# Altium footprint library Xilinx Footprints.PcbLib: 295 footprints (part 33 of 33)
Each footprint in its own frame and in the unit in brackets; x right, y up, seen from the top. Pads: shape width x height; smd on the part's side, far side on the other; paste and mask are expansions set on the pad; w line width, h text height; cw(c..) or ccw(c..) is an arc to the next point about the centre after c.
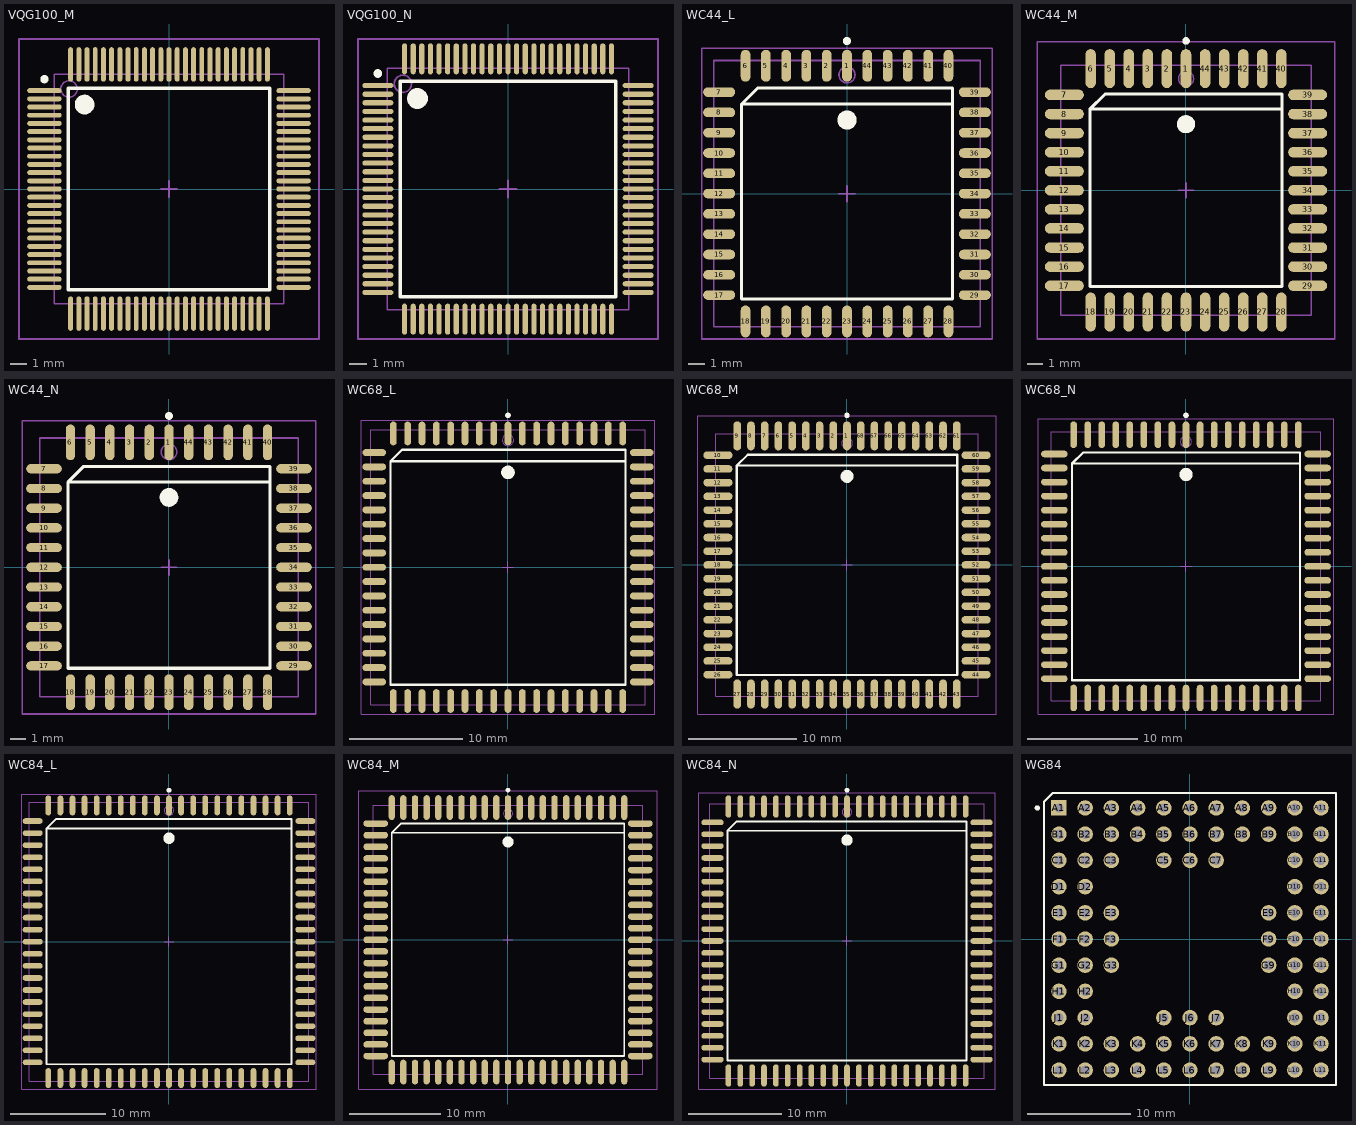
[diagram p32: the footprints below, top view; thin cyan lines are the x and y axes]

## VQG100_M [mm] "100-Pin Very Thin Quad Flat Pack (VQG100) - Pb-Free, IPC Low Density"
height 1.2
pads (100):
  oval 2.1x0.3 smd: 1(-7.6,6) 2(-7.6,5.5) 3(-7.6,5) 4(-7.6,4.5) 5(-7.6,4) 6(-7.6,3.5) 7(-7.6,3) 8(-7.6,2.5) 9(-7.6,2) 10(-7.6,1.5) 11(-7.6,1) 12(-7.6,0.5) 13(-7.6,0) 14(-7.6,-0.5) 15(-7.6,-1) 16(-7.6,-1.5) 17(-7.6,-2) 18(-7.6,-2.5) 19(-7.6,-3) 20(-7.6,-3.5) 21(-7.6,-4) 22(-7.6,-4.5) 23(-7.6,-5) 24(-7.6,-5.5) 25(-7.6,-6) 51(7.6,-6) 52(7.6,-5.5) 53(7.6,-5) 54(7.6,-4.5) 55(7.6,-4) 56(7.6,-3.5) 57(7.6,-3) 58(7.6,-2.5) 59(7.6,-2) 60(7.6,-1.5) 61(7.6,-1) 62(7.6,-0.5) 63(7.6,0) 64(7.6,0.5) 65(7.6,1) 66(7.6,1.5) 67(7.6,2) 68(7.6,2.5) 69(7.6,3) 70(7.6,3.5) 71(7.6,4) 72(7.6,4.5) 73(7.6,5) 74(7.6,5.5) 75(7.6,6)
  oval 0.3x2.1 smd: 26(-6,-7.6) 27(-5.5,-7.6) 28(-5,-7.6) 29(-4.5,-7.6) 30(-4,-7.6) 31(-3.5,-7.6) 32(-3,-7.6) 33(-2.5,-7.6) 34(-2,-7.6) 35(-1.5,-7.6) 36(-1,-7.6) 37(-0.5,-7.6) 38(0,-7.6) 39(0.5,-7.6) 40(1,-7.6) 41(1.5,-7.6) 42(2,-7.6) 43(2.5,-7.6) 44(3,-7.6) 45(3.5,-7.6) 46(4,-7.6) 47(4.5,-7.6) 48(5,-7.6) 49(5.5,-7.6) 50(6,-7.6) 76(6,7.6) 77(5.5,7.6) 78(5,7.6) 79(4.5,7.6) 80(4,7.6) 81(3.5,7.6) 82(3,7.6) 83(2.5,7.6) 84(2,7.6) 85(1.5,7.6) 86(1,7.6) 87(0.5,7.6) 88(0,7.6) 89(-0.5,7.6) 90(-1,7.6) 91(-1.5,7.6) 92(-2,7.6) 93(-2.5,7.6) 94(-3,7.6) 95(-3.5,7.6) 96(-4,7.6) 97(-4.5,7.6) 98(-5,7.6) 99(-5.5,7.6) 100(-6,7.6)
Top Overlay:
  circle w0.6: c-5.15,5.15 r0.3
  circle w0.25: c-7.6,6.7 r0.125
  lines w0.2: -6.15,-6.15 6.15,-6.15 6.15,6.15 -6.15,6.15 -6.15,-6.15
Mechanical 13:
  circle w0.1: c-6.1,6.1 r0.5
  lines w0.1: -7,-7 7,-7 7,7 -7,7 -7,-7
Mechanical 15:
  lines w0.1: -0.5,0 0.5,0 ; 0,-0.5 0,0.5 ; -9.15,-9.15 9.15,-9.15 9.15,9.15 -9.15,9.15 -9.15,-9.15
3D body: height 1.2, standoff 0, extent -7,-7 7,7

## VQG100_N [mm] "100-Pin Very Thin Quad Flat Pack (VQG100) - Pb-Free, IPC Medium Density"
height 1.2
pads (100):
  oval 1.8x0.3 smd: 1(-7.55,6) 2(-7.55,5.5) 3(-7.55,5) 4(-7.55,4.5) 5(-7.55,4) 6(-7.55,3.5) 7(-7.55,3) 8(-7.55,2.5) 9(-7.55,2) 10(-7.55,1.5) 11(-7.55,1) 12(-7.55,0.5) 13(-7.55,0) 14(-7.55,-0.5) 15(-7.55,-1) 16(-7.55,-1.5) 17(-7.55,-2) 18(-7.55,-2.5) 19(-7.55,-3) 20(-7.55,-3.5) 21(-7.55,-4) 22(-7.55,-4.5) 23(-7.55,-5) 24(-7.55,-5.5) 25(-7.55,-6) 51(7.55,-6) 52(7.55,-5.5) 53(7.55,-5) 54(7.55,-4.5) 55(7.55,-4) 56(7.55,-3.5) 57(7.55,-3) 58(7.55,-2.5) 59(7.55,-2) 60(7.55,-1.5) 61(7.55,-1) 62(7.55,-0.5) 63(7.55,0) 64(7.55,0.5) 65(7.55,1) 66(7.55,1.5) 67(7.55,2) 68(7.55,2.5) 69(7.55,3) 70(7.55,3.5) 71(7.55,4) 72(7.55,4.5) 73(7.55,5) 74(7.55,5.5) 75(7.55,6)
  oval 0.3x1.8 smd: 26(-6,-7.55) 27(-5.5,-7.55) 28(-5,-7.55) 29(-4.5,-7.55) 30(-4,-7.55) 31(-3.5,-7.55) 32(-3,-7.55) 33(-2.5,-7.55) 34(-2,-7.55) 35(-1.5,-7.55) 36(-1,-7.55) 37(-0.5,-7.55) 38(0,-7.55) 39(0.5,-7.55) 40(1,-7.55) 41(1.5,-7.55) 42(2,-7.55) 43(2.5,-7.55) 44(3,-7.55) 45(3.5,-7.55) 46(4,-7.55) 47(4.5,-7.55) 48(5,-7.55) 49(5.5,-7.55) 50(6,-7.55) 76(6,7.55) 77(5.5,7.55) 78(5,7.55) 79(4.5,7.55) 80(4,7.55) 81(3.5,7.55) 82(3,7.55) 83(2.5,7.55) 84(2,7.55) 85(1.5,7.55) 86(1,7.55) 87(0.5,7.55) 88(0,7.55) 89(-0.5,7.55) 90(-1,7.55) 91(-1.5,7.55) 92(-2,7.55) 93(-2.5,7.55) 94(-3,7.55) 95(-3.5,7.55) 96(-4,7.55) 97(-4.5,7.55) 98(-5,7.55) 99(-5.5,7.55) 100(-6,7.55)
Top Overlay:
  circle w0.6: c-5.25,5.25 r0.3
  circle w0.25: c-7.55,6.7 r0.125
  lines w0.2: -6.25,-6.25 6.25,-6.25 6.25,6.25 -6.25,6.25 -6.25,-6.25
Mechanical 13:
  circle w0.1: c-6.1,6.1 r0.5
  lines w0.1: -7,-7 7,-7 7,7 -7,7 -7,-7
Mechanical 15:
  lines w0.1: -0.5,0 0.5,0 ; 0,-0.5 0,0.5 ; -8.7,-8.7 8.7,-8.7 8.7,8.7 -8.7,8.7 -8.7,-8.7
3D body: height 1.2, standoff 0, extent -7,-7 7,7

## WC44_L [mm] "44-Pin Window Ceramic Leaded Chip Carrier (WC44), IPC High Density"
height 4.83
pads (44):
  oval 0.6x2 smd: 1(0,8) 2(-1.27,8) 3(-2.54,8) 4(-3.81,8) 5(-5.08,8) 6(-6.35,8) 18(-6.35,-8) 19(-5.08,-8) 20(-3.81,-8) 21(-2.54,-8) 22(-1.27,-8) 23(0,-8) 24(1.27,-8) 25(2.54,-8) 26(3.81,-8) 27(5.08,-8) 28(6.35,-8) 40(6.35,8) 41(5.08,8) 42(3.81,8) 43(2.54,8) 44(1.27,8)
  oval 2x0.6 smd: 7(-8,6.35) 8(-8,5.08) 9(-8,3.81) 10(-8,2.54) 11(-8,1.27) 12(-8,0) 13(-8,-1.27) 14(-8,-2.54) 15(-8,-3.81) 16(-8,-5.08) 17(-8,-6.35) 29(8,-6.35) 30(8,-5.08) 31(8,-3.81) 32(8,-2.54) 33(8,-1.27) 34(8,0) 35(8,1.27) 36(8,2.54) 37(8,3.81) 38(8,5.08) 39(8,6.35)
Top Overlay:
  circle w0.25: c0,9.55 r0.125
  circle w0.6: c0,4.6 r0.3
  lines w0.2: 6.6,5.6 -6.6,5.6 ; -6.6,5.6 -5.6,6.6 6.6,6.6 6.6,-6.6 -6.6,-6.6 -6.6,5.6
Mechanical 13:
  circle w0.1: c0,7.43 r0.5
  lines w0.1: -8.33,-8.33 -8.33,8.33 8.33,8.33 8.33,-8.33 -8.33,-8.33
Mechanical 15:
  lines w0.1: -0.5,0 0.5,0 ; 0,-0.5 0,0.5 ; -9.1,-9.1 -9.1,9.1 9.1,9.1 9.1,-9.1 -9.1,-9.1
3D body: height 4.83, standoff 0, extent -8.33,-8.33 8.33,8.33

## WC44_M [mm] "44-Pin Window Ceramic Leaded Chip Carrier (WC44), IPC Low Density"
height 4.83
pads (44):
  oval 0.7x2.6 smd: 1(0,8.1) 2(-1.27,8.1) 3(-2.54,8.1) 4(-3.81,8.1) 5(-5.08,8.1) 6(-6.35,8.1) 18(-6.35,-8.1) 19(-5.08,-8.1) 20(-3.81,-8.1) 21(-2.54,-8.1) 22(-1.27,-8.1) 23(0,-8.1) 24(1.27,-8.1) 25(2.54,-8.1) 26(3.81,-8.1) 27(5.08,-8.1) 28(6.35,-8.1) 40(6.35,8.1) 41(5.08,8.1) 42(3.81,8.1) 43(2.54,8.1) 44(1.27,8.1)
  oval 2.6x0.7 smd: 7(-8.1,6.35) 8(-8.1,5.08) 9(-8.1,3.81) 10(-8.1,2.54) 11(-8.1,1.27) 12(-8.1,0) 13(-8.1,-1.27) 14(-8.1,-2.54) 15(-8.1,-3.81) 16(-8.1,-5.08) 17(-8.1,-6.35) 29(8.1,-6.35) 30(8.1,-5.08) 31(8.1,-3.81) 32(8.1,-2.54) 33(8.1,-1.27) 34(8.1,0) 35(8.1,1.27) 36(8.1,2.54) 37(8.1,3.81) 38(8.1,5.08) 39(8.1,6.35)
Top Overlay:
  circle w0.25: c0,9.95 r0.125
  circle w0.6: c0,4.4 r0.3
  lines w0.2: 6.4,5.4 -6.4,5.4 ; -6.4,5.4 -5.4,6.4 6.4,6.4 6.4,-6.4 -6.4,-6.4 -6.4,5.4
Mechanical 13:
  circle w0.1: c0,7.43 r0.5
  lines w0.1: -8.33,-8.33 -8.33,8.33 8.33,8.33 8.33,-8.33 -8.33,-8.33
Mechanical 15:
  lines w0.1: -0.5,0 0.5,0 ; 0,-0.5 0,0.5 ; -9.9,-9.9 -9.9,9.9 9.9,9.9 9.9,-9.9 -9.9,-9.9
3D body: height 4.83, standoff 0, extent -8.33,-8.33 8.33,8.33

## WC44_N [mm] "44-Pin Window Ceramic Leaded Chip Carrier (WC44), IPC Medium Density"
height 4.83
pads (44):
  oval 0.6x2.3 smd: 1(0,8.05) 2(-1.27,8.05) 3(-2.54,8.05) 4(-3.81,8.05) 5(-5.08,8.05) 6(-6.35,8.05) 18(-6.35,-8.05) 19(-5.08,-8.05) 20(-3.81,-8.05) 21(-2.54,-8.05) 22(-1.27,-8.05) 23(0,-8.05) 24(1.27,-8.05) 25(2.54,-8.05) 26(3.81,-8.05) 27(5.08,-8.05) 28(6.35,-8.05) 40(6.35,8.05) 41(5.08,8.05) 42(3.81,8.05) 43(2.54,8.05) 44(1.27,8.05)
  oval 2.3x0.6 smd: 7(-8.05,6.35) 8(-8.05,5.08) 9(-8.05,3.81) 10(-8.05,2.54) 11(-8.05,1.27) 12(-8.05,0) 13(-8.05,-1.27) 14(-8.05,-2.54) 15(-8.05,-3.81) 16(-8.05,-5.08) 17(-8.05,-6.35) 29(8.05,-6.35) 30(8.05,-5.08) 31(8.05,-3.81) 32(8.05,-2.54) 33(8.05,-1.27) 34(8.05,0) 35(8.05,1.27) 36(8.05,2.54) 37(8.05,3.81) 38(8.05,5.08) 39(8.05,6.35)
Top Overlay:
  circle w0.25: c0,9.75 r0.125
  circle w0.6: c0,4.5 r0.3
  lines w0.2: 6.5,5.5 -6.5,5.5 ; -6.5,5.5 -5.5,6.5 6.5,6.5 6.5,-6.5 -6.5,-6.5 -6.5,5.5
Mechanical 13:
  circle w0.1: c0,7.43 r0.5
  lines w0.1: -8.33,-8.33 -8.33,8.33 8.33,8.33 8.33,-8.33 -8.33,-8.33
Mechanical 15:
  lines w0.1: -0.5,0 0.5,0 ; 0,-0.5 0,0.5 ; -9.45,-9.45 -9.45,9.45 9.45,9.45 9.45,-9.45 -9.45,-9.45
3D body: height 4.83, standoff 0, extent -8.33,-8.33 8.33,8.33

## WC68_L [mm] "68-Pin Window Ceramic Leaded Chip Carrier (WC68), IPC High Density"
height 4.83
pads (68):
  oval 0.6x2.1 smd: 1(0,11.85) 2(-1.27,11.85) 3(-2.54,11.85) 4(-3.81,11.85) 5(-5.08,11.85) 6(-6.35,11.85) 7(-7.62,11.85) 8(-8.89,11.85) 9(-10.16,11.85) 27(-10.16,-11.85) 28(-8.89,-11.85) 29(-7.62,-11.85) 30(-6.35,-11.85) 31(-5.08,-11.85) 32(-3.81,-11.85) 33(-2.54,-11.85) 34(-1.27,-11.85) 35(0,-11.85) 36(1.27,-11.85) 37(2.54,-11.85) 38(3.81,-11.85) 39(5.08,-11.85) 40(6.35,-11.85) 41(7.62,-11.85) 42(8.89,-11.85) 43(10.16,-11.85) 61(10.16,11.85) 62(8.89,11.85) 63(7.62,11.85) 64(6.35,11.85) 65(5.08,11.85) 66(3.81,11.85) 67(2.54,11.85) 68(1.27,11.85)
  oval 2.1x0.6 smd: 10(-11.85,10.16) 11(-11.85,8.89) 12(-11.85,7.62) 13(-11.85,6.35) 14(-11.85,5.08) 15(-11.85,3.81) 16(-11.85,2.54) 17(-11.85,1.27) 18(-11.85,0) 19(-11.85,-1.27) 20(-11.85,-2.54) 21(-11.85,-3.81) 22(-11.85,-5.08) 23(-11.85,-6.35) 24(-11.85,-7.62) 25(-11.85,-8.89) 26(-11.85,-10.16) 44(11.85,-10.16) 45(11.85,-8.89) 46(11.85,-7.62) 47(11.85,-6.35) 48(11.85,-5.08) 49(11.85,-3.81) 50(11.85,-2.54) 51(11.85,-1.27) 52(11.85,0) 53(11.85,1.27) 54(11.85,2.54) 55(11.85,3.81) 56(11.85,5.08) 57(11.85,6.35) 58(11.85,7.62) 59(11.85,8.89) 60(11.85,10.16)
Top Overlay:
  circle w0.25: c0,13.45 r0.125
  circle w0.6: c0,8.4 r0.3
  lines w0.2: 10.4,9.4 -10.4,9.4 ; -10.4,9.4 -9.4,10.4 10.4,10.4 10.4,-10.4 -10.4,-10.4 -10.4,9.4
Mechanical 13:
  circle w0.1: c0,11.265 r0.5
  lines w0.1: -12.165,-12.165 -12.165,12.165 12.165,12.165 12.165,-12.165 -12.165,-12.165
Mechanical 15:
  lines w0.1: -0.5,0 0.5,0 ; 0,-0.5 0,0.5 ; -13,-13 -13,13 13,13 13,-13 -13,-13
3D body: height 4.83, standoff 0, extent -12.165,-12.165 12.165,12.165

## WC68_M [mm] "68-Pin Window Ceramic Leaded Chip Carrier (WC68), IPC Low Density"
height 4.83
pads (68):
  oval 0.7x2.7 smd: 1(0,11.95) 2(-1.27,11.95) 3(-2.54,11.95) 4(-3.81,11.95) 5(-5.08,11.95) 6(-6.35,11.95) 7(-7.62,11.95) 8(-8.89,11.95) 9(-10.16,11.95) 27(-10.16,-11.95) 28(-8.89,-11.95) 29(-7.62,-11.95) 30(-6.35,-11.95) 31(-5.08,-11.95) 32(-3.81,-11.95) 33(-2.54,-11.95) 34(-1.27,-11.95) 35(0,-11.95) 36(1.27,-11.95) 37(2.54,-11.95) 38(3.81,-11.95) 39(5.08,-11.95) 40(6.35,-11.95) 41(7.62,-11.95) 42(8.89,-11.95) 43(10.16,-11.95) 61(10.16,11.95) 62(8.89,11.95) 63(7.62,11.95) 64(6.35,11.95) 65(5.08,11.95) 66(3.81,11.95) 67(2.54,11.95) 68(1.27,11.95)
  oval 2.7x0.7 smd: 10(-11.95,10.16) 11(-11.95,8.89) 12(-11.95,7.62) 13(-11.95,6.35) 14(-11.95,5.08) 15(-11.95,3.81) 16(-11.95,2.54) 17(-11.95,1.27) 18(-11.95,0) 19(-11.95,-1.27) 20(-11.95,-2.54) 21(-11.95,-3.81) 22(-11.95,-5.08) 23(-11.95,-6.35) 24(-11.95,-7.62) 25(-11.95,-8.89) 26(-11.95,-10.16) 44(11.95,-10.16) 45(11.95,-8.89) 46(11.95,-7.62) 47(11.95,-6.35) 48(11.95,-5.08) 49(11.95,-3.81) 50(11.95,-2.54) 51(11.95,-1.27) 52(11.95,0) 53(11.95,1.27) 54(11.95,2.54) 55(11.95,3.81) 56(11.95,5.08) 57(11.95,6.35) 58(11.95,7.62) 59(11.95,8.89) 60(11.95,10.16)
Top Overlay:
  circle w0.25: c0,13.85 r0.125
  circle w0.6: c0,8.2 r0.3
  lines w0.2: 10.2,9.2 -10.2,9.2 ; -10.2,9.2 -9.2,10.2 10.2,10.2 10.2,-10.2 -10.2,-10.2 -10.2,9.2
Mechanical 13:
  circle w0.1: c0,11.265 r0.5
  lines w0.1: -12.165,-12.165 -12.165,12.165 12.165,12.165 12.165,-12.165 -12.165,-12.165
Mechanical 15:
  lines w0.1: -0.5,0 0.5,0 ; 0,-0.5 0,0.5 ; -13.8,-13.8 -13.8,13.8 13.8,13.8 13.8,-13.8 -13.8,-13.8
3D body: height 4.83, standoff 0, extent -12.165,-12.165 12.165,12.165

## WC68_N [mm] "68-Pin Window Ceramic Leaded Chip Carrier (WC68), IPC Medium Density"
height 4.83
pads (68):
  oval 0.6x2.4 smd: 1(0,11.9) 2(-1.27,11.9) 3(-2.54,11.9) 4(-3.81,11.9) 5(-5.08,11.9) 6(-6.35,11.9) 7(-7.62,11.9) 8(-8.89,11.9) 9(-10.16,11.9) 27(-10.16,-11.9) 28(-8.89,-11.9) 29(-7.62,-11.9) 30(-6.35,-11.9) 31(-5.08,-11.9) 32(-3.81,-11.9) 33(-2.54,-11.9) 34(-1.27,-11.9) 35(0,-11.9) 36(1.27,-11.9) 37(2.54,-11.9) 38(3.81,-11.9) 39(5.08,-11.9) 40(6.35,-11.9) 41(7.62,-11.9) 42(8.89,-11.9) 43(10.16,-11.9) 61(10.16,11.9) 62(8.89,11.9) 63(7.62,11.9) 64(6.35,11.9) 65(5.08,11.9) 66(3.81,11.9) 67(2.54,11.9) 68(1.27,11.9)
  oval 2.4x0.6 smd: 10(-11.9,10.16) 11(-11.9,8.89) 12(-11.9,7.62) 13(-11.9,6.35) 14(-11.9,5.08) 15(-11.9,3.81) 16(-11.9,2.54) 17(-11.9,1.27) 18(-11.9,0) 19(-11.9,-1.27) 20(-11.9,-2.54) 21(-11.9,-3.81) 22(-11.9,-5.08) 23(-11.9,-6.35) 24(-11.9,-7.62) 25(-11.9,-8.89) 26(-11.9,-10.16) 44(11.9,-10.16) 45(11.9,-8.89) 46(11.9,-7.62) 47(11.9,-6.35) 48(11.9,-5.08) 49(11.9,-3.81) 50(11.9,-2.54) 51(11.9,-1.27) 52(11.9,0) 53(11.9,1.27) 54(11.9,2.54) 55(11.9,3.81) 56(11.9,5.08) 57(11.9,6.35) 58(11.9,7.62) 59(11.9,8.89) 60(11.9,10.16)
Top Overlay:
  circle w0.25: c0,13.65 r0.125
  circle w0.6: c0,8.3 r0.3
  lines w0.2: 10.3,9.3 -10.3,9.3 ; -10.3,9.3 -9.3,10.3 10.3,10.3 10.3,-10.3 -10.3,-10.3 -10.3,9.3
Mechanical 13:
  circle w0.1: c0,11.265 r0.5
  lines w0.1: -12.165,-12.165 -12.165,12.165 12.165,12.165 12.165,-12.165 -12.165,-12.165
Mechanical 15:
  lines w0.1: -0.5,0 0.5,0 ; 0,-0.5 0,0.5 ; -13.35,-13.35 -13.35,13.35 13.35,13.35 13.35,-13.35 -13.35,-13.35
3D body: height 4.83, standoff 0, extent -12.165,-12.165 12.165,12.165

## WC84_L [mm] "84-Pin Window Ceramic Leaded Chip Carrier (WC84), IPC High Density"
height 4.83
pads (84):
  oval 0.6x2.1 smd: 1(0,14.35) 2(-1.27,14.35) 3(-2.54,14.35) 4(-3.81,14.35) 5(-5.08,14.35) 6(-6.35,14.35) 7(-7.62,14.35) 8(-8.89,14.35) 9(-10.16,14.35) 10(-11.43,14.35) 11(-12.7,14.35) 33(-12.7,-14.35) 34(-11.43,-14.35) 35(-10.16,-14.35) 36(-8.89,-14.35) 37(-7.62,-14.35) 38(-6.35,-14.35) 39(-5.08,-14.35) 40(-3.81,-14.35) 41(-2.54,-14.35) 42(-1.27,-14.35) 43(0,-14.35) 44(1.27,-14.35) 45(2.54,-14.35) 46(3.81,-14.35) 47(5.08,-14.35) 48(6.35,-14.35) 49(7.62,-14.35) 50(8.89,-14.35) 51(10.16,-14.35) 52(11.43,-14.35) 53(12.7,-14.35) 75(12.7,14.35) 76(11.43,14.35) 77(10.16,14.35) 78(8.89,14.35) 79(7.62,14.35) 80(6.35,14.35) 81(5.08,14.35) 82(3.81,14.35) 83(2.54,14.35) 84(1.27,14.35)
  oval 2.1x0.6 smd: 12(-14.35,12.7) 13(-14.35,11.43) 14(-14.35,10.16) 15(-14.35,8.89) 16(-14.35,7.62) 17(-14.35,6.35) 18(-14.35,5.08) 19(-14.35,3.81) 20(-14.35,2.54) 21(-14.35,1.27) 22(-14.35,0) 23(-14.35,-1.27) 24(-14.35,-2.54) 25(-14.35,-3.81) 26(-14.35,-5.08) 27(-14.35,-6.35) 28(-14.35,-7.62) 29(-14.35,-8.89) 30(-14.35,-10.16) 31(-14.35,-11.43) 32(-14.35,-12.7) 54(14.35,-12.7) 55(14.35,-11.43) 56(14.35,-10.16) 57(14.35,-8.89) 58(14.35,-7.62) 59(14.35,-6.35) 60(14.35,-5.08) 61(14.35,-3.81) 62(14.35,-2.54) 63(14.35,-1.27) 64(14.35,0) 65(14.35,1.27) 66(14.35,2.54) 67(14.35,3.81) 68(14.35,5.08) 69(14.35,6.35) 70(14.35,7.62) 71(14.35,8.89) 72(14.35,10.16) 73(14.35,11.43) 74(14.35,12.7)
Top Overlay:
  circle w0.25: c0,15.95 r0.125
  circle w0.6: c0,10.9 r0.3
  lines w0.2: 12.9,11.9 -12.9,11.9 ; -12.9,11.9 -11.9,12.9 12.9,12.9 12.9,-12.9 -12.9,-12.9 -12.9,11.9
Mechanical 13:
  circle w0.1: c0,13.805 r0.5
  lines w0.1: -14.705,-14.705 -14.705,14.705 14.705,14.705 14.705,-14.705 -14.705,-14.705
Mechanical 15:
  lines w0.1: -0.5,0 0.5,0 ; 0,-0.5 0,0.5 ; -15.5,-15.5 -15.5,15.5 15.5,15.5 15.5,-15.5 -15.5,-15.5
3D body: height 4.83, standoff 0, extent -14.705,-14.705 14.705,14.705

## WC84_M [mm] "84-Pin Window Ceramic Leaded Chip Carrier (WC84), IPC Low Density"
height 4.83
pads (84):
  oval 0.7x2.7 smd: 1(0,14.45) 2(-1.27,14.45) 3(-2.54,14.45) 4(-3.81,14.45) 5(-5.08,14.45) 6(-6.35,14.45) 7(-7.62,14.45) 8(-8.89,14.45) 9(-10.16,14.45) 10(-11.43,14.45) 11(-12.7,14.45) 33(-12.7,-14.45) 34(-11.43,-14.45) 35(-10.16,-14.45) 36(-8.89,-14.45) 37(-7.62,-14.45) 38(-6.35,-14.45) 39(-5.08,-14.45) 40(-3.81,-14.45) 41(-2.54,-14.45) 42(-1.27,-14.45) 43(0,-14.45) 44(1.27,-14.45) 45(2.54,-14.45) 46(3.81,-14.45) 47(5.08,-14.45) 48(6.35,-14.45) 49(7.62,-14.45) 50(8.89,-14.45) 51(10.16,-14.45) 52(11.43,-14.45) 53(12.7,-14.45) 75(12.7,14.45) 76(11.43,14.45) 77(10.16,14.45) 78(8.89,14.45) 79(7.62,14.45) 80(6.35,14.45) 81(5.08,14.45) 82(3.81,14.45) 83(2.54,14.45) 84(1.27,14.45)
  oval 2.7x0.7 smd: 12(-14.45,12.7) 13(-14.45,11.43) 14(-14.45,10.16) 15(-14.45,8.89) 16(-14.45,7.62) 17(-14.45,6.35) 18(-14.45,5.08) 19(-14.45,3.81) 20(-14.45,2.54) 21(-14.45,1.27) 22(-14.45,0) 23(-14.45,-1.27) 24(-14.45,-2.54) 25(-14.45,-3.81) 26(-14.45,-5.08) 27(-14.45,-6.35) 28(-14.45,-7.62) 29(-14.45,-8.89) 30(-14.45,-10.16) 31(-14.45,-11.43) 32(-14.45,-12.7) 54(14.45,-12.7) 55(14.45,-11.43) 56(14.45,-10.16) 57(14.45,-8.89) 58(14.45,-7.62) 59(14.45,-6.35) 60(14.45,-5.08) 61(14.45,-3.81) 62(14.45,-2.54) 63(14.45,-1.27) 64(14.45,0) 65(14.45,1.27) 66(14.45,2.54) 67(14.45,3.81) 68(14.45,5.08) 69(14.45,6.35) 70(14.45,7.62) 71(14.45,8.89) 72(14.45,10.16) 73(14.45,11.43) 74(14.45,12.7)
Top Overlay:
  circle w0.25: c0,16.35 r0.125
  circle w0.6: c0,10.7 r0.3
  lines w0.2: 12.7,11.7 -12.7,11.7 ; -12.7,11.7 -11.7,12.7 12.7,12.7 12.7,-12.7 -12.7,-12.7 -12.7,11.7
Mechanical 13:
  circle w0.1: c0,13.805 r0.5
  lines w0.1: -14.705,-14.705 -14.705,14.705 14.705,14.705 14.705,-14.705 -14.705,-14.705
Mechanical 15:
  lines w0.1: -0.5,0 0.5,0 ; 0,-0.5 0,0.5 ; -16.3,-16.3 -16.3,16.3 16.3,16.3 16.3,-16.3 -16.3,-16.3
3D body: height 4.83, standoff 0, extent -14.705,-14.705 14.705,14.705

## WC84_N [mm] "84-Pin Window Ceramic Leaded Chip Carrier (WC84), IPC Medium Density"
height 4.83
pads (84):
  oval 0.6x2.4 smd: 1(0,14.4) 2(-1.27,14.4) 3(-2.54,14.4) 4(-3.81,14.4) 5(-5.08,14.4) 6(-6.35,14.4) 7(-7.62,14.4) 8(-8.89,14.4) 9(-10.16,14.4) 10(-11.43,14.4) 11(-12.7,14.4) 33(-12.7,-14.4) 34(-11.43,-14.4) 35(-10.16,-14.4) 36(-8.89,-14.4) 37(-7.62,-14.4) 38(-6.35,-14.4) 39(-5.08,-14.4) 40(-3.81,-14.4) 41(-2.54,-14.4) 42(-1.27,-14.4) 43(0,-14.4) 44(1.27,-14.4) 45(2.54,-14.4) 46(3.81,-14.4) 47(5.08,-14.4) 48(6.35,-14.4) 49(7.62,-14.4) 50(8.89,-14.4) 51(10.16,-14.4) 52(11.43,-14.4) 53(12.7,-14.4) 75(12.7,14.4) 76(11.43,14.4) 77(10.16,14.4) 78(8.89,14.4) 79(7.62,14.4) 80(6.35,14.4) 81(5.08,14.4) 82(3.81,14.4) 83(2.54,14.4) 84(1.27,14.4)
  oval 2.4x0.6 smd: 12(-14.4,12.7) 13(-14.4,11.43) 14(-14.4,10.16) 15(-14.4,8.89) 16(-14.4,7.62) 17(-14.4,6.35) 18(-14.4,5.08) 19(-14.4,3.81) 20(-14.4,2.54) 21(-14.4,1.27) 22(-14.4,0) 23(-14.4,-1.27) 24(-14.4,-2.54) 25(-14.4,-3.81) 26(-14.4,-5.08) 27(-14.4,-6.35) 28(-14.4,-7.62) 29(-14.4,-8.89) 30(-14.4,-10.16) 31(-14.4,-11.43) 32(-14.4,-12.7) 54(14.4,-12.7) 55(14.4,-11.43) 56(14.4,-10.16) 57(14.4,-8.89) 58(14.4,-7.62) 59(14.4,-6.35) 60(14.4,-5.08) 61(14.4,-3.81) 62(14.4,-2.54) 63(14.4,-1.27) 64(14.4,0) 65(14.4,1.27) 66(14.4,2.54) 67(14.4,3.81) 68(14.4,5.08) 69(14.4,6.35) 70(14.4,7.62) 71(14.4,8.89) 72(14.4,10.16) 73(14.4,11.43) 74(14.4,12.7)
Top Overlay:
  circle w0.25: c0,16.15 r0.125
  circle w0.6: c0,10.8 r0.3
  lines w0.2: 12.8,11.8 -12.8,11.8 ; -12.8,11.8 -11.8,12.8 12.8,12.8 12.8,-12.8 -12.8,-12.8 -12.8,11.8
Mechanical 13:
  circle w0.1: c0,13.805 r0.5
  lines w0.1: -14.705,-14.705 -14.705,14.705 14.705,14.705 14.705,-14.705 -14.705,-14.705
Mechanical 15:
  lines w0.1: -0.5,0 0.5,0 ; 0,-0.5 0,0.5 ; -15.85,-15.85 -15.85,15.85 15.85,15.85 15.85,-15.85 -15.85,-15.85
3D body: height 4.83, standoff 0, extent -14.705,-14.705 14.705,14.705

## WG84 [mm] "84-Pin Ceramic Window Pin Grid Array (WG84)"
height 4.93
pads (85):
  rect 1.5x1.5 hole 0.9: A1(-12.7,12.7)
  round 1.5 hole 0.9: A2(-10.16,12.7) A3(-7.62,12.7) A4(-5.08,12.7) A5(-2.54,12.7) A6(0,12.7) A7(2.54,12.7) A8(5.08,12.7) A9(7.62,12.7) A10(10.16,12.7) A11(12.7,12.7) B1(-12.7,10.16) B2(-10.16,10.16) B3(-7.62,10.16) B4(-5.08,10.16) B5(-2.54,10.16) B6(0,10.16) B7(2.54,10.16) B8(5.08,10.16) B9(7.62,10.16) B10(10.16,10.16) B11(12.7,10.16) C1(-12.7,7.62) C2(-10.16,7.62) C3(-7.62,7.62) C5(-2.54,7.62) C6(0,7.62) C7(2.54,7.62) C10(10.16,7.62) C11(12.7,7.62) D1(-12.7,5.08) D2(-10.16,5.08) D10(10.16,5.08) D11(12.7,5.08) E1(-12.7,2.54) E2(-10.16,2.54) E3(-7.62,2.54) E9(7.62,2.54) E10(10.16,2.54) E11(12.7,2.54) F1(-12.7,0) F2(-10.16,0) F3(-7.62,0) F9(7.62,0) F10(10.16,0) F11(12.7,0) G1(-12.7,-2.54) G2(-10.16,-2.54) G3(-7.62,-2.54) G9(7.62,-2.54) G10(10.16,-2.54) G11(12.7,-2.54) H1(-12.7,-5.08) H2(-10.16,-5.08) H10(10.16,-5.08) H11(12.7,-5.08) J1(-12.7,-7.62) J2(-10.16,-7.62) J5(-2.54,-7.62) J6(0,-7.62) J7(2.54,-7.62) J10(10.16,-7.62) J11(12.7,-7.62) K1(-12.7,-10.16) K2(-10.16,-10.16) K3(-7.62,-10.16) K4(-5.08,-10.16) K5(-2.54,-10.16) K6(0,-10.16) K7(2.54,-10.16) K8(5.08,-10.16) K9(7.62,-10.16) K10(10.16,-10.16) K11(12.7,-10.16) L1(-12.7,-12.7) L2(-10.16,-12.7) L3(-7.62,-12.7) L4(-5.08,-12.7) L5(-2.54,-12.7) L6(0,-12.7) L7(2.54,-12.7) L8(5.08,-12.7) L9(7.62,-12.7) L10(10.16,-12.7) L11(12.7,-12.7)
Top Overlay:
  circle w0.25: c-14.8,12.7 r0.125
  lines w0.2: -14.15,-14.15 -14.15,13.316 -13.316,14.15 14.15,14.15 14.15,-14.15 -14.15,-14.15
